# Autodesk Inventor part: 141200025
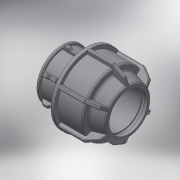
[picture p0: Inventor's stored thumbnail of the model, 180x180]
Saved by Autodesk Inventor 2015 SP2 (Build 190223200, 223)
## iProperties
Created: 2017-08
Part Number: 141200025
Material: Generic
Description: PLASSON L.14 END PLUG (SILVER) 25
Document SubType Name: Modeling
Designer: KIM
Density: 1 g/cm^3
Appearance: Default
Author: KIM
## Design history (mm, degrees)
derived "141200.ipt"
feature "Solid1::141200.ipt"
tag "TaggingFeature1"
body "Solid1"
other parameters: "d1" = 25, "d4" = 15 deg, "d5" = 31.68, "d6" = 10.4544, "d16" = 25.5, "d17" = 2.4, "d18" = 59, "d24" = 2.4, "d25" = 45, "d26" = 37.5, "d27" = 2.4, "d28" = 135 deg, "d29" = 1.44, "d31" = 1.25, "d44" = 0.5, "d46" = 150 deg, "d49" = 2.5, "d50" = 0, "d51" = 1.5, "d52" = 1, "d53" = 45 deg, "d54" = 11.8, "d55" = 4.72, "d56" = 2.5, "d57" = 0, "d58" = 0.75, "d59" = 0.5, "d61" = 360 deg, "d66" = 32.5, "d68" = 48, "d69" = 1.77, "d_" = 25, "H_" = 59, "l_" = 48
